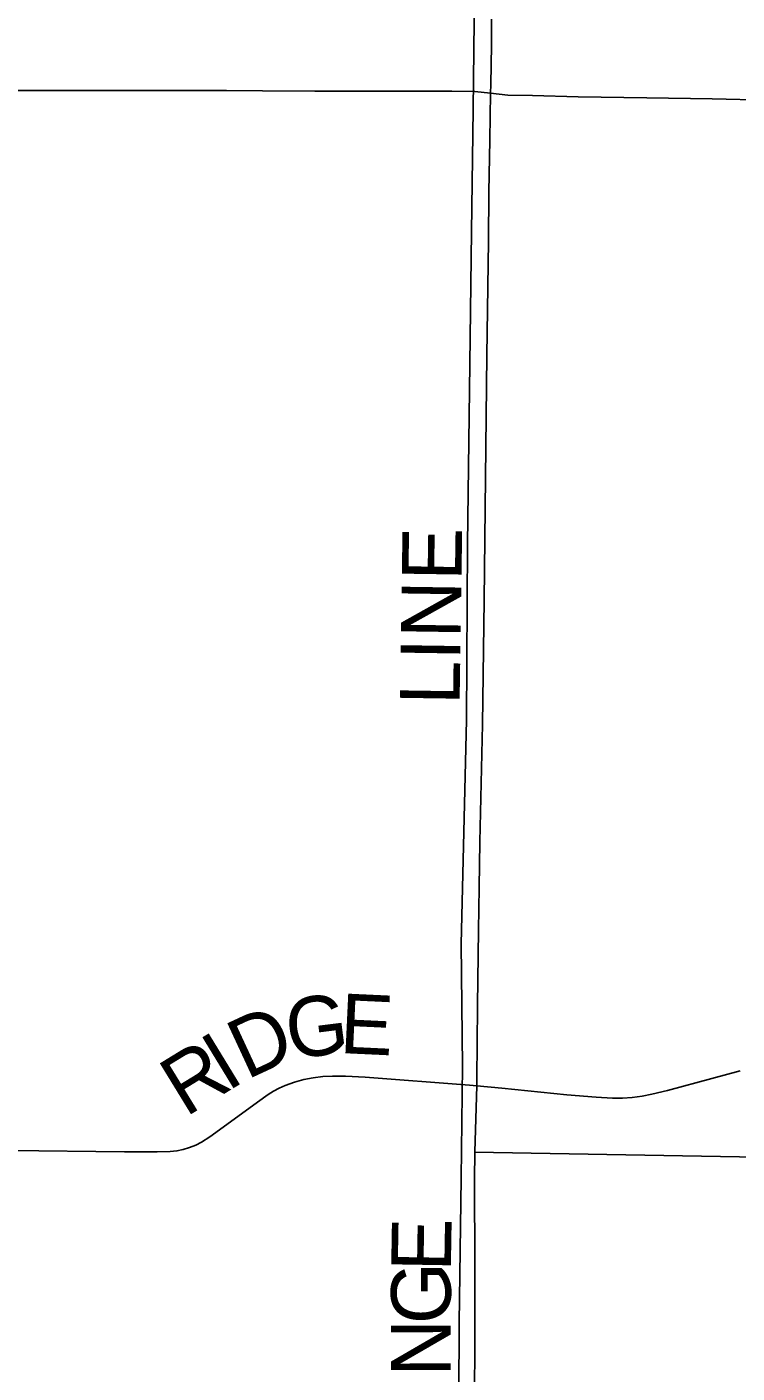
# Model space of a CAD drawing. Extents: x 0 to 680, y 0 to 834.
# Drawn here: x 94.87 to 120.84, y 268.89 to 318.11 of the extents above; entities that cross this region are included whole.
import ezdxf

# ---------------------------------------------------------------- set-up
doc = ezdxf.new("R2010")
doc.units = 0
for name, color, linetype in [('GM_X_County_Road', 7, 'Continuous'), ('GM_X_County_Road_Text', 7, 'Continuous'), ('GM_X_Minor_River', 7, 'Continuous'), ('GM_X_Township_Road', 7, 'Continuous'), ('GM_X_Township_Road_Text', 7, 'Continuous')]:
    doc.layers.add(name, color=color, linetype=linetype)

msp = doc.modelspace()

# ---------------------------------------------------------------- linework, layer by layer
at = {"layer": 'GM_X_County_Road'}
for points in [[(100.239, 277.005), (100.355, 277.017), (100.592, 277.064), (100.823, 277.136), (101.046, 277.23), (101.26, 277.342), (101.566, 277.533), (102.053, 277.881), (103.304, 278.801), (103.692, 279.076), (103.894, 279.2), (104.102, 279.31), (104.318, 279.408), (104.651, 279.53), (104.994, 279.622), (105.344, 279.689), (105.696, 279.734), (106.051, 279.753), (106.527, 279.749), (107.241, 279.716), (111.05, 279.417), (111.325, 279.391)], [(111.325, 279.391), (112.238, 279.307), (114.615, 279.071), (115.687, 278.982), (116.284, 278.95), (116.644, 278.947), (117.005, 278.968), (117.362, 279.017), (117.715, 279.087), (118.296, 279.228), (119.91, 279.667), (120.946, 279.949)], [(83.757, 277.077), (85.068, 277.073), (87.098, 277.064), (88.769, 277.055), (90.321, 277.055), (91.634, 277.042), (94.261, 277.037), (98.44, 276.987), (99.634, 276.98), (100.115, 276.992), (100.239, 277.005)]]:
    msp.add_lwpolyline(points, dxfattribs=at)
at = {"layer": 'GM_X_Minor_River'}
msp.add_lwpolyline([(111.183, 222.254), (111.21, 228.212), (111.295, 235.947), (111.318, 237.316), (110.388, 238.264), (110.488, 242.545), (110.478, 249.772), (110.583, 256.108), (110.635, 262.723), (110.681, 270.736), (110.754, 276.024), (110.793, 280.118), (110.751, 284.592), (110.946, 292.764), (110.98, 299.204), (111.059, 304.828), (111.126, 310.626), (111.186, 315.099), (111.243, 319.426)], dxfattribs=at)
at = {"layer": 'GM_X_Township_Road'}
msp.add_line((111.252, 276.982), (111.325, 279.391), dxfattribs=at)
for points in [[(111.825, 315.686), (111.83, 316.011), (111.858, 317.443), (111.864, 318.398)], [(72.981, 315.841), (73.527, 315.83), (74.601, 315.807), (75.675, 315.803), (79.495, 315.81), (81.285, 315.799), (82.598, 315.79), (84.031, 315.799), (85.582, 315.803), (90.238, 315.789), (92.625, 315.781), (94.177, 315.783), (95.49, 315.792), (102.175, 315.786), (103.488, 315.775), (105.398, 315.767), (107.666, 315.764), (110.412, 315.76), (111.247, 315.749), (111.825, 315.686)], [(111.325, 279.391), (111.328, 279.719), (111.338, 280.913), (111.352, 282.346), (111.389, 285.092), (111.411, 286.643), (111.437, 288.315), (111.527, 292.612), (111.591, 297.148), (111.691, 306.103), (111.746, 310.281), (111.766, 312.071), (111.801, 313.982), (111.825, 315.686)], [(111.825, 315.686), (112.46, 315.616), (113.358, 315.599), (115.031, 315.56), (117.54, 315.521), (119.93, 315.485), (121.961, 315.436), (123.395, 315.424), (125.187, 315.395), (126.621, 315.375), (131.639, 315.29), (133.432, 315.282), (136.897, 315.232), (141.677, 315.169), (144.784, 315.132), (146.576, 315.1), (148.727, 315.083), (150.16, 315.012), (150.637, 315.013), (150.995, 315.037), (151.232, 315.071), (151.428, 315.098)], [(111.072, 237.987), (111.111, 238.177), (111.117, 238.296), (111.107, 238.763), (111.108, 240.076), (111.104, 241.031), (111.122, 245.925), (111.14, 249.984), (111.153, 251.535), (111.156, 254.043), (111.204, 257.385), (111.222, 259.653), (111.231, 261.204), (111.23, 262.398), (111.239, 263.711), (111.24, 265.979), (111.24, 267.77), (111.249, 270.277), (111.249, 272.425), (111.244, 273.738), (111.239, 275.051), (111.241, 276.006), (111.251, 276.944), (111.252, 276.982)], [(111.242, 276.965), (228.132, 274.916), (231.712, 274.79), (234.217, 274.711), (236.245, 274.646), (239.705, 274.555), (244.836, 274.407), (247.699, 274.316), (249.369, 274.266), (253.425, 274.135), (255.215, 274.078), (257.83, 273.986), (260.573, 273.913), (263.437, 273.841), (265.584, 273.782), (266.506, 273.748)]]:
    msp.add_lwpolyline(points, dxfattribs=at)

# ---------------------------------------------------------------- texts
at = {"layer": 'GM_X_County_Road_Text'}
for s, rotation, p in [('G', 7.1399, (104.473, 280.363)), ('E', 357.3249, (106.28, 280.598)), ('D', 24.8901, (102.903, 279.604)), ('I', 31.4055, (102.196, 279.168)), ('R', 31.5019, (100.669, 278.232))]:
    msp.add_text(s, height=2.182, rotation=rotation, dxfattribs=at).set_placement(p)
at = {"layer": 'GM_X_Township_Road_Text'}
for s, height, rotation, p in [('LINE', 2.1818, 89.141, (110.691, 293.311)), ('E', 2.182, 89.0486, (110.371, 272.595)), ('G', 2.182, 89.9708, (110.371, 270.684)), ('N', 2.182, 90, (110.371, 268.764))]:
    msp.add_text(s, height=height, rotation=rotation, dxfattribs=at).set_placement(p)

doc.saveas('drawing.dxf')
